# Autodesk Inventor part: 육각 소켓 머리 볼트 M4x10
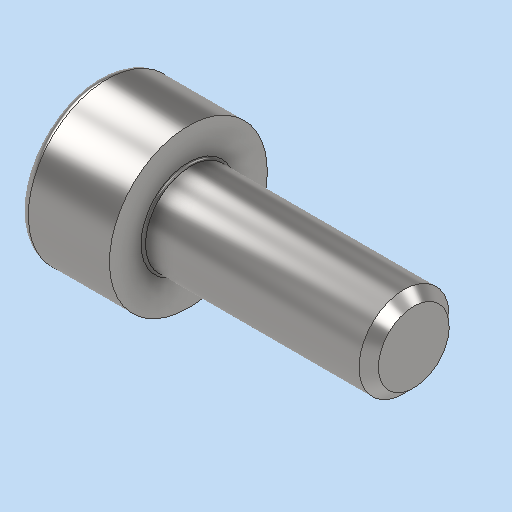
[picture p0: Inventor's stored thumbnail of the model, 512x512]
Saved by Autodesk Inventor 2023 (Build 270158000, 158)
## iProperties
Created: 2024-11
Part Number: 육각 소켓 머리 볼트 M4x10
Material: 강철, 연강
Description: 6각머리 태핑 나사
Document SubType Name: Modeling
Designer: asung
Density: 7.85 g/cm^3
Appearance: 기본값
Author: jhkim
Sending System: Autodesk Inventor 2025
Preprocessor: ST-DEVELOPER v20
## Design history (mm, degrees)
feature "Solid1"
node "솔리드1"
